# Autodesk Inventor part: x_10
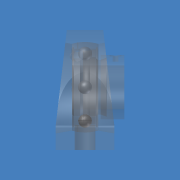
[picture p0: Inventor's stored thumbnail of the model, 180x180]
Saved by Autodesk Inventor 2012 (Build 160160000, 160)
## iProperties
Company: CAD-Verlag
Part Number: x_10
Document SubType Name: Modeling
Created: 2004-09
Material: Standard
Designer: Greiling
Manufacturer: Standard
Standards Organization: Custom
Density: 1 g/cm^3
Control State: 0
Master: False
Checked Out: False
Shininess: 64.0
Length Units: 11269
Angle Units: 11279
Time Units: 11290
Mass Units: 11283
Length Display Precision: 3
Angle Display Precision: 2
Compacted: True
Übersetzungsnorm: STEP AP214CD
Dateiname: w2c22665.stp
Vorprozessor: ACIS
Postprozessor: Build: 081d, Release: 8 SP1 - Date: Tue 01/26/2004
Gesendete Einheiten: MILLIMETERS
Unbestimmtheit: 1e-06
Density: 0.0
Volumn: 0.0
Area: 0.0
PropertySet Name: Model Information
Author: Jürgen Kronas
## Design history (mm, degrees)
feature "Basis1"
node "Volumenkörper1"
node "Volumenkörpern"
node "Oberflächenkörpern"
